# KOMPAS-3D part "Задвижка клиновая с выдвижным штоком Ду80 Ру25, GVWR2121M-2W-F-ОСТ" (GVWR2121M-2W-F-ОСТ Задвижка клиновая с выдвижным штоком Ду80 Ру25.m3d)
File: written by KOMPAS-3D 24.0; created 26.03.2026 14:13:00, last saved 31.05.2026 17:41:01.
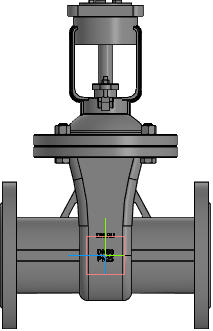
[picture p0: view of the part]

Document properties: Автор: R2D2; Полное имя файла: E:\Работа\Зайцев\GVWR2121M-2W-F-ОСТ Задвижка клиновая 30с964нж DN.ru Ду50-300 Ру25\исходные материалы\DN80\DN80\GVWR2121M-2W-F-ОСТ Задвижка клиновая с выдвижным штоком Ду80 Ру25.m3d

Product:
- Part/product: Задвижка клиновая с выдвижным штоком Ду80 Ру25  | designation GVWR2121M-2W-F-ОСТ
    Масса: 24
    Раздел спецификации: Прочие изделия
    Примечание: D040-08603

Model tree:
1. Операция без истории:1

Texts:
  GVWR2121M-2W-F-ОСТ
